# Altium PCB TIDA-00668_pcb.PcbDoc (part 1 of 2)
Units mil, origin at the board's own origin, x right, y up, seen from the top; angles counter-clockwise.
Board outline 2510.03 x 1760.03 mil, 4 copper layers (Component Side 1, Signal Layer 2, Signal Layer 3, Solder Side 4), stack 60.634 mil thick; 105 components, 46 nets, 336 pads, 4 vias.
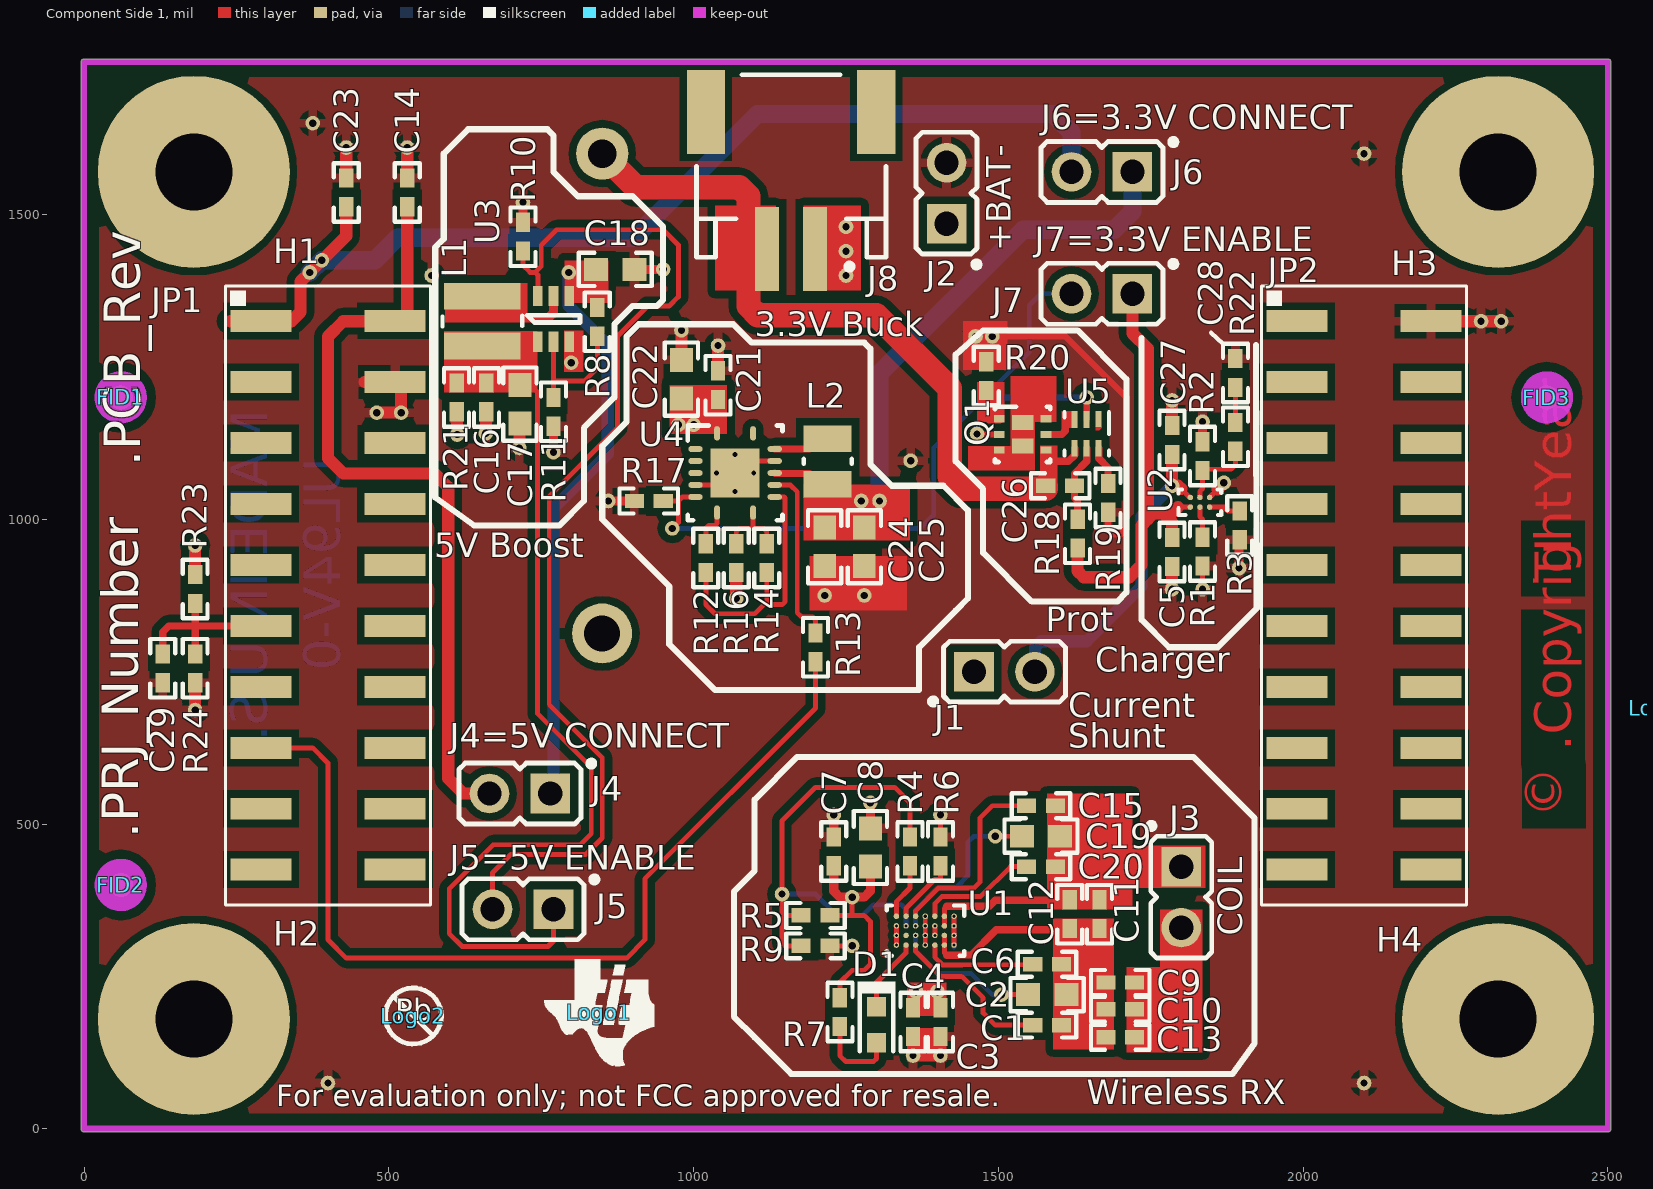
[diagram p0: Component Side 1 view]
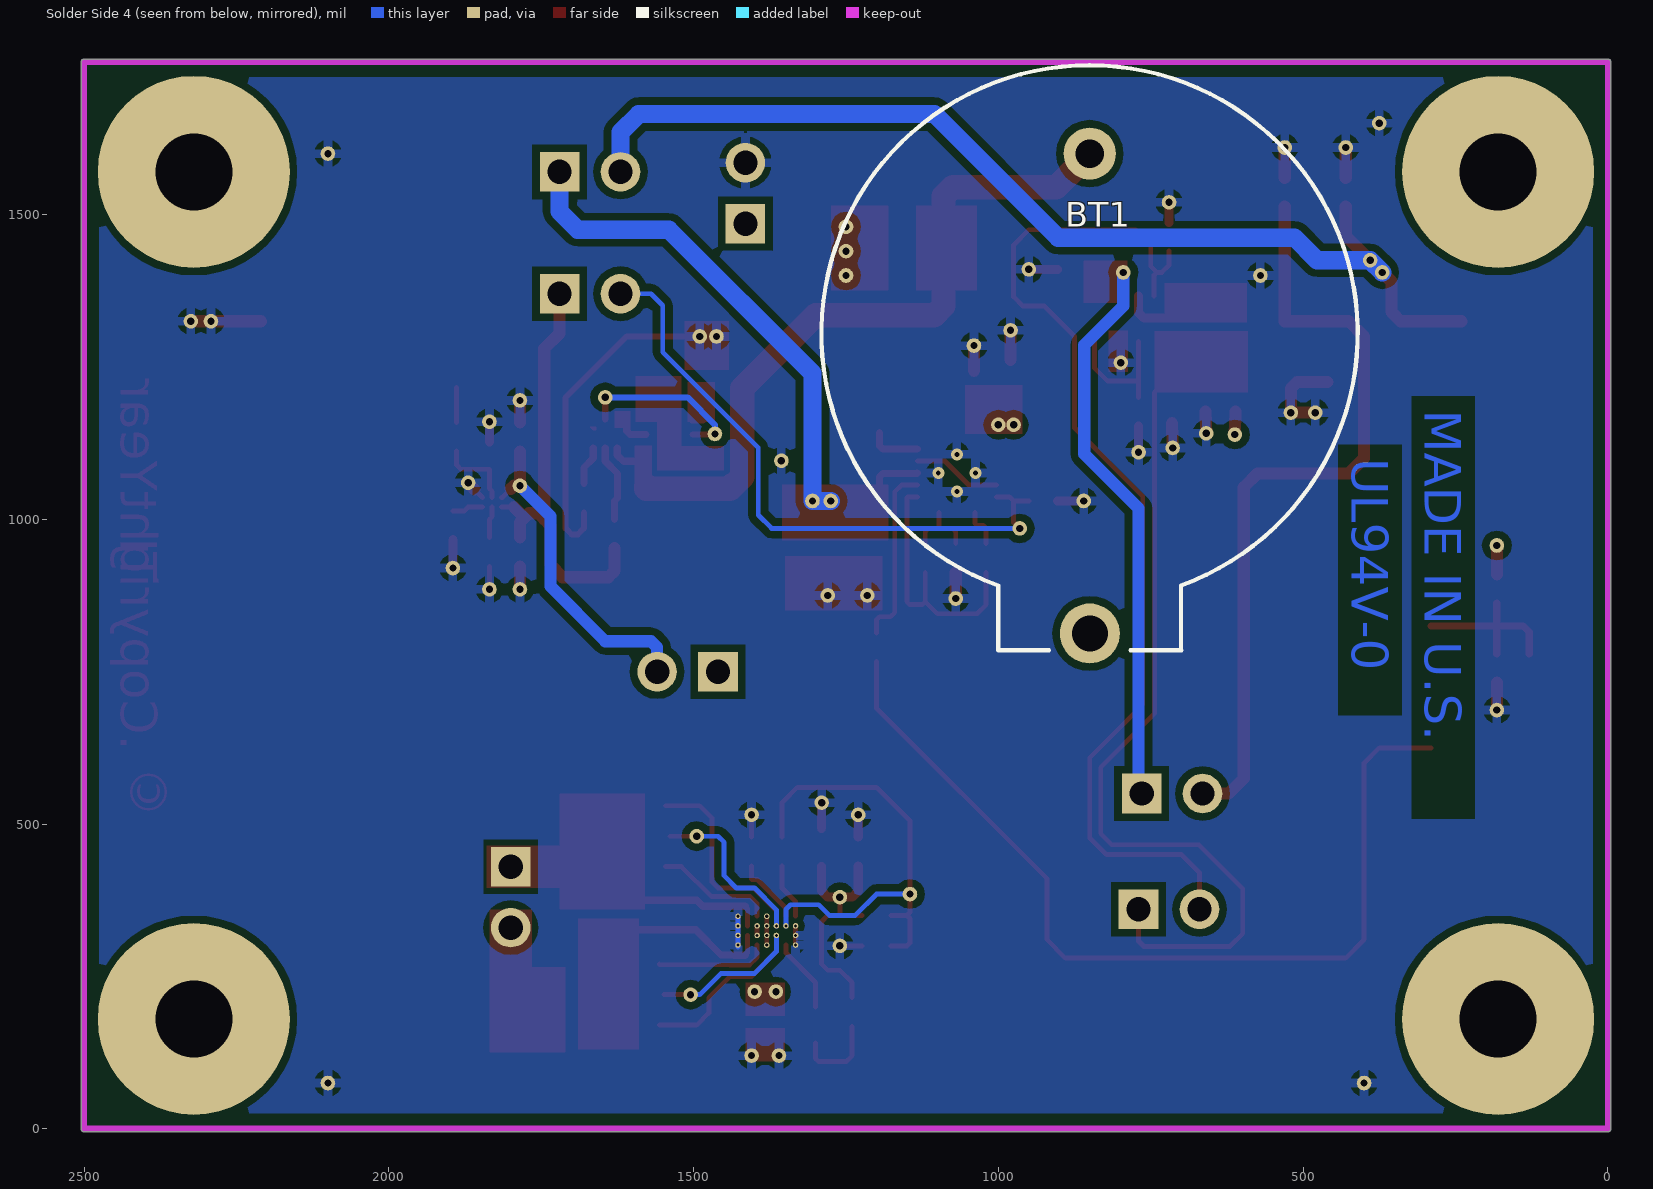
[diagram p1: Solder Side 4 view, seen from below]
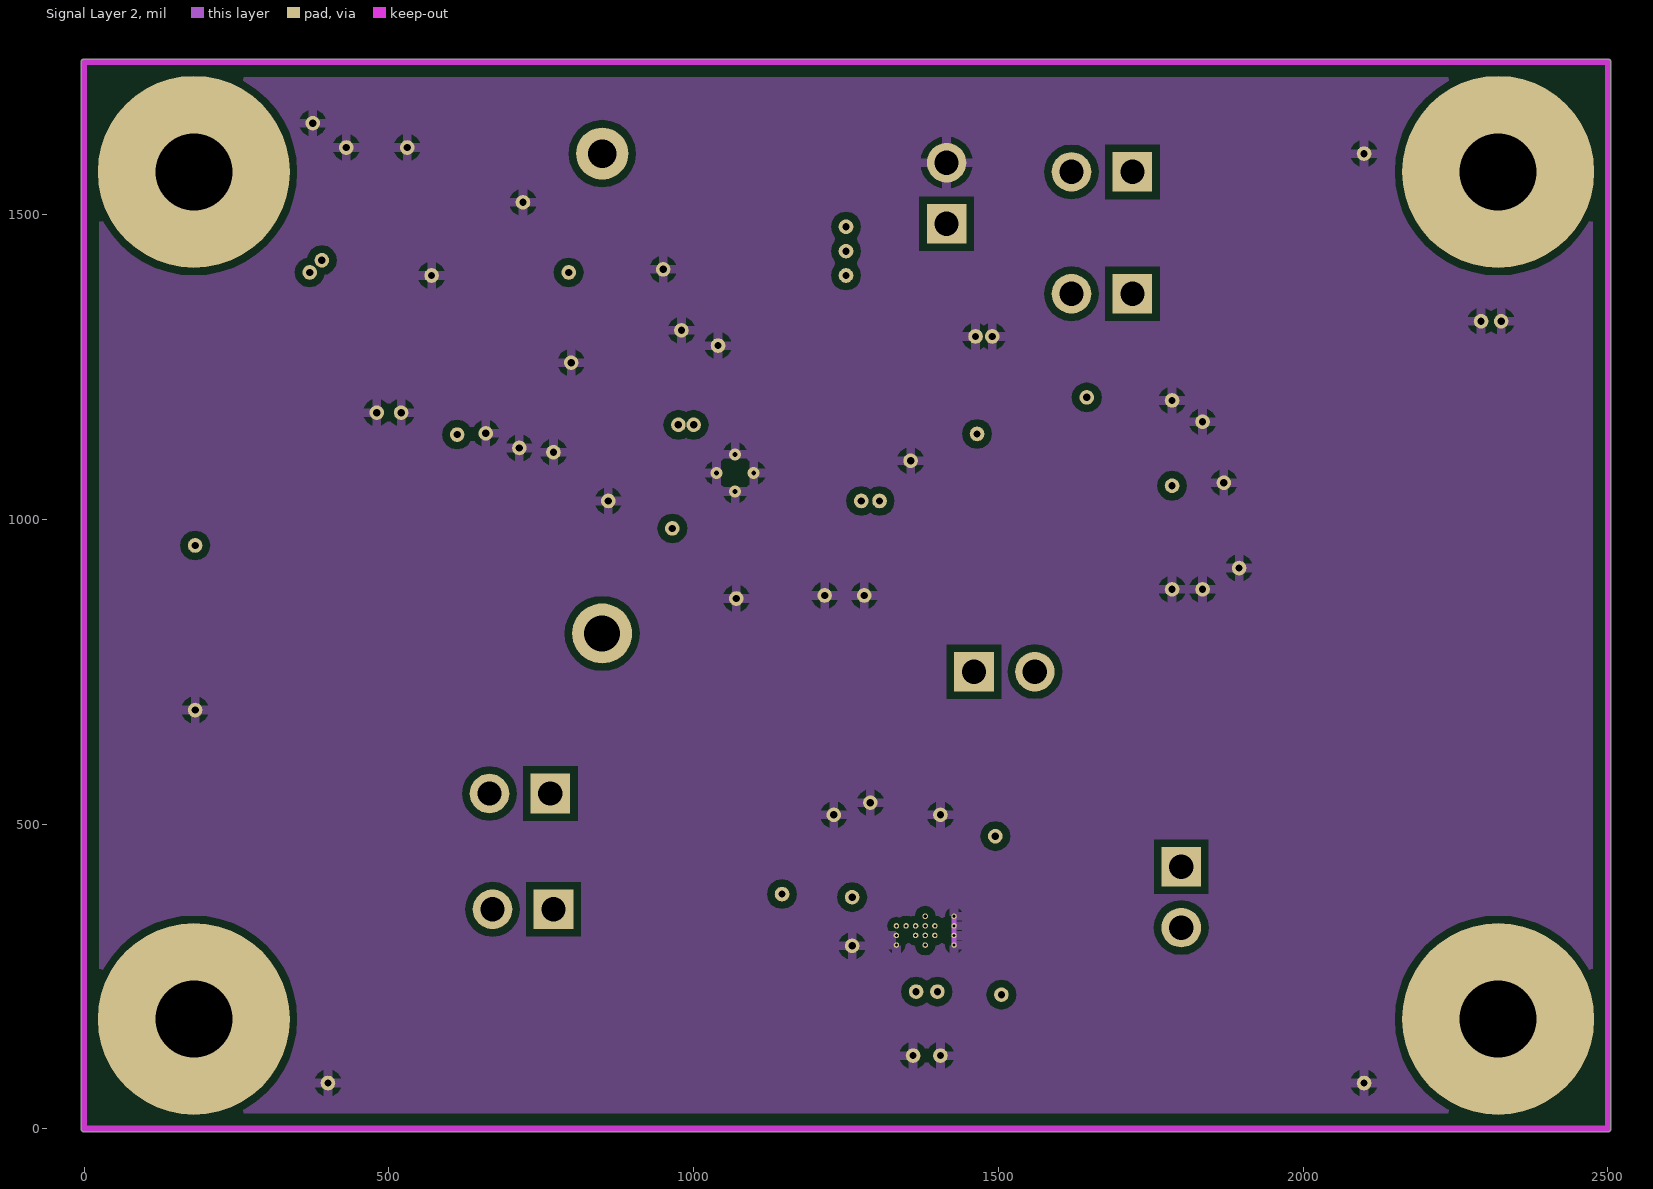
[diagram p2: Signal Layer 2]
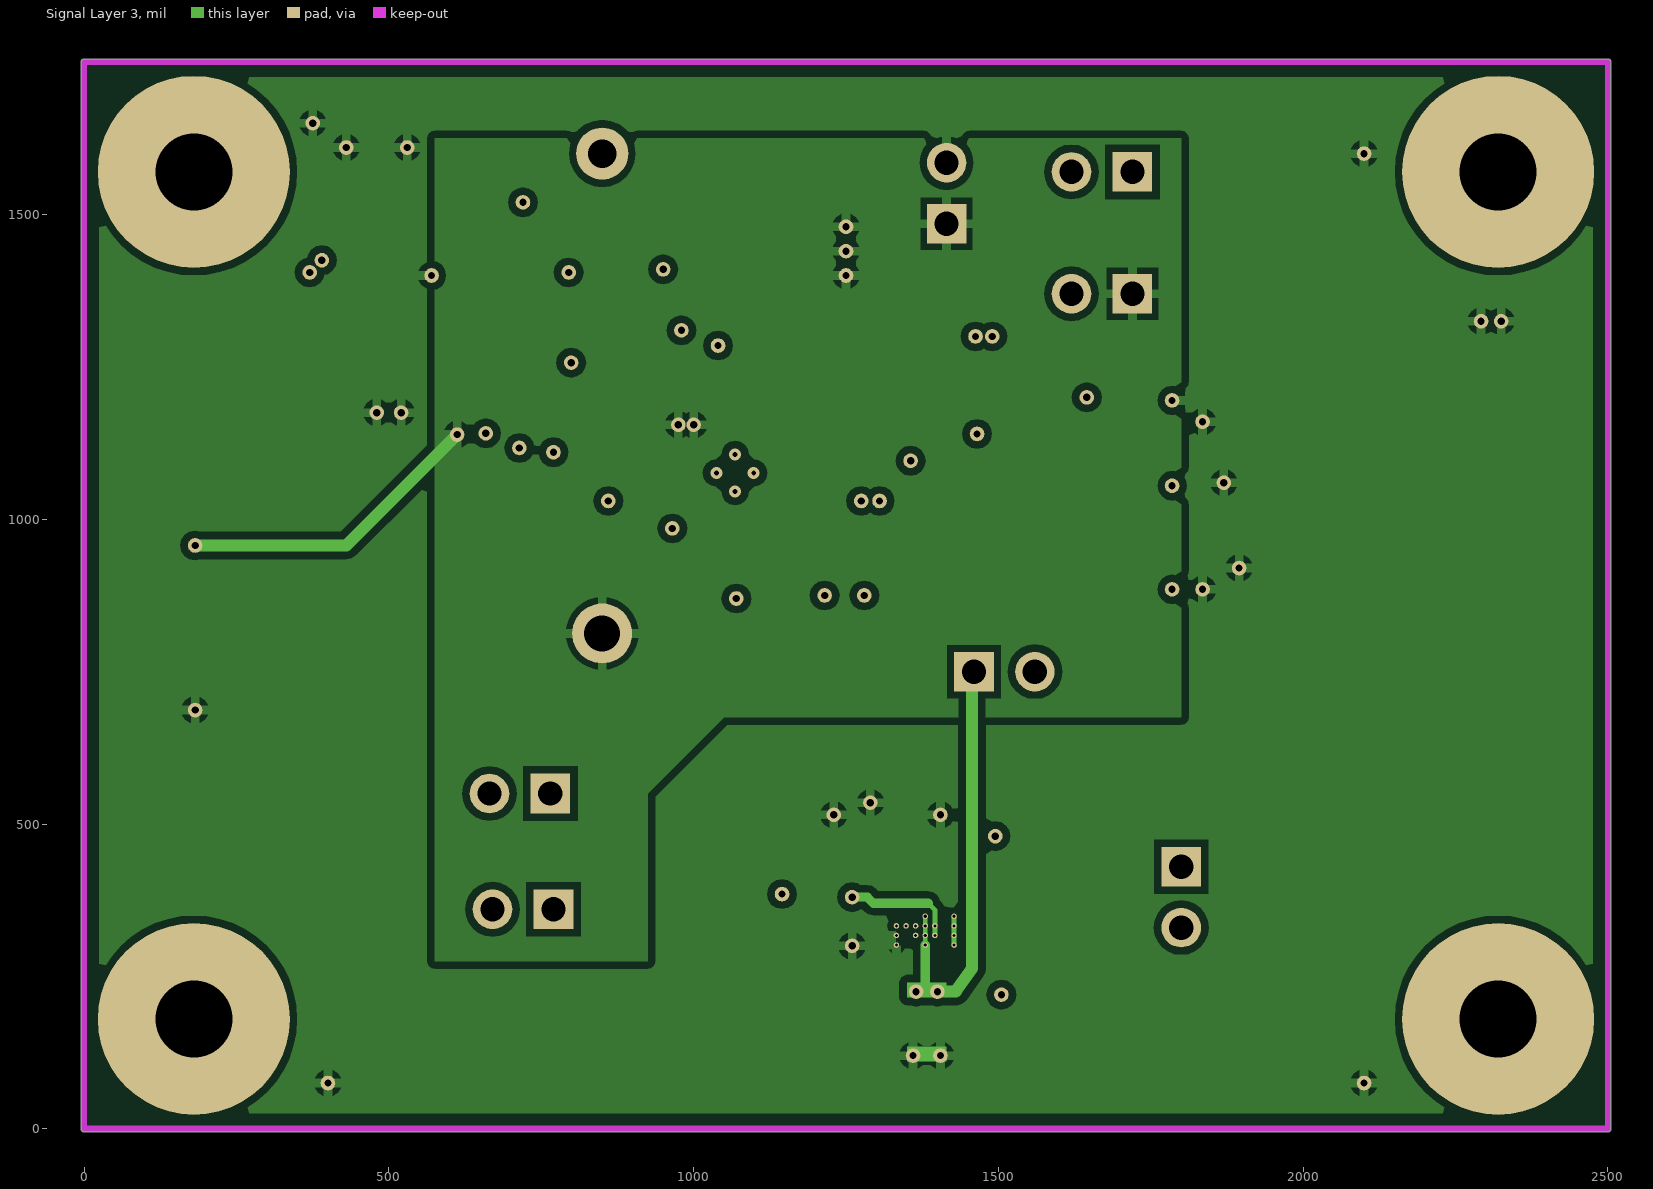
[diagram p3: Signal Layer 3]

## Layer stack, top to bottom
Top Solder: solder mask 0.4, Solder Resist, Dk 3.5
Component Side 1: signal copper 1.4
Dielectric 1: core 10, FR-4HT, Dk 4.2
Signal Layer 2: signal copper 1.417
Dielectric 2: prepreg 35, Dk 4.2
Signal Layer 3: signal copper 1.417
Dielectric 3: core 10, FR-4HT, Dk 4.2
Solder Side 4: signal copper 1.4
Bottom Solder: solder mask 0.4, Solder Resist, Dk 3.5

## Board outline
0,-5.02 cw(c0,0) -5.01,0 -5.01,1750 cw(c0,1750) 0,1755.01 2500,1755.01 cw(c2500,1750) 2505.01,1750 2505.01,0 cw(c2500,0) 2500,-5.02

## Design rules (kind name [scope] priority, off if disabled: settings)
AcuteAngle [All] p1: minimum=4.50000000000000E+0001 checktracksonly=FALSE
AssemblyTestPointUsage [All] p1: valid=2
Clearance Clearance_Keepouts [((IsTrack Or IsArc) And Not InPoly) And IsFree and IsKeepOut vs ((IsTrack Or IsArc) And Not InPoly) And IsFree and IsKeepOut] p1: gap=0
Clearance Clearance_BoardEdge_MountingHoles [OnCopper and InComponentClass('Mounting Holes') vs IsKeepOut] p2: gap=15
Clearance Clearance_BoardEdge_Poly [OnCopper and InPoly vs IsKeepOut] p3: gap=15
Clearance Clearance_BoardEdge [OnCopper and Not InComponentClass('Logo') and not InComponentClass('FiducialMark') and not InRegion(1000,500,4000,800) and Not IsKeepout vs IsKeepOut] p4: gap=40
Clearance Clearance_Poly [InPolygon] p5: gap=12
Clearance [All] p6: gap=3.9
ComponentClearance ComponentClearance_MountingHoles_FiducialMarks [InComponentClass('Mounting Holes') vs InComponentClass('FiducialMark')] p1: gap=50 collisioncheckmode=3 verticalgap=10 showdistances=FALSE
ComponentClearance ComponentClearance_Shunt [InComponentClass('Header') vs InComponentClass('Shunt')] p2: gap=0 collisioncheckmode=3 verticalgap=0 showdistances=FALSE
ComponentClearance ComponentClearance_Logo [InComponentClass('Logo')] p3: gap=30 collisioncheckmode=3 verticalgap=10 showdistances=FALSE
ComponentClearance ComponentClearance_ScrewToNut [(HasFootprint('NY PMS 440 0025 PH')) vs (HasFootprint('Keystone_1902C'))] p4: gap=5 collisioncheckmode=3 verticalgap=10 showdistances=FALSE
ComponentClearance ComponentClearance_MountingHoles [InComponentClass('Mounting Holes')] p5: gap=20 collisioncheckmode=3 verticalgap=100000 showdistances=FALSE
ComponentClearance ComponentClearance_SmallPassives [HasFootprint('0201*') or HasFootprint('0402*') or HasFootprint('0508') or HasFootprint('0603*') or HasFootprint('0612') or HasFootprint('0805*') or HasFootprint('0815*') or HasFootprint('0830*') or HasFootprint('1206*') or HasFootprint('1210*') or HasFootprint('1808*') or HasFootprint('1812*') or HasFootprint('1825*') or HasFootprint('2010*') or HasFootprint('2220*') or HasFootprint('2225*') or HasFootprint('2512*') or HasFootprint('2728*') or HasFootprint('3518*') vs HasFootprint('0201*') or HasFootprint('0402*') or HasFootprint('0508') or HasFootprint('0603*') or HasFootprint('0612') or HasFootprint('0805*') or HasFootprint('0815*') or HasFootprint('0830*') or HasFootprint('1206*') or HasFootprint('1210*') or HasFootprint('1808*') or HasFootprint('1812*') or HasFootprint('1825*') or HasFootprint('2010*') or HasFootprint('2220*') or HasFootprint('2225*') or HasFootprint('2512*') or HasFootprint('2728*') or HasFootprint('3518*')] p6: gap=12 collisioncheckmode=3 verticalgap=12 showdistances=FALSE
ComponentClearance ComponentClearance_THtoSMT [IsThruComponent vs IsSMTComponent] p7: gap=12 collisioncheckmode=3 verticalgap=12 showdistances=FALSE
ComponentClearance ComponentClearance_THtoTH [IsThruComponent vs IsThruComponent] p8: gap=12 collisioncheckmode=3 verticalgap=12 showdistances=FALSE
ComponentClearance [All] p9: gap=12 collisioncheckmode=3 verticalgap=12 showdistances=FALSE
DiffPairsRouting [All] p1: maxlimit=100 minlimit=10 mostfreqgap=10 toplayer_minwidth=15 toplayer_maxwidth=15 toplayer_prefwidth=15 midlayer1_minwidth=15 midlayer1_maxwidth=15 midlayer1_prefwidth=15 midlayer2_minwidth=15 midlayer2_maxwidth=15 midlayer2_prefwidth=15 bottomlayer_minwidth=15 bottomlayer_maxwidth=15 bottomlayer_prefwidth=15 maxuncoupledlength=1000
FabricationTestPointUsage TestPointUsage [All] p1: valid=2 allowmultiple=FALSE
FabricationTestpoint Testpoint [All] p1: side=3 testpointundercomponent=TRUE minsize=40 maxsize=100 preferedsize=60 minholesize=0 maxholesize=40 preferedholesize=32 testpointgrid=1 allowsidetop=TRUE allowsidebottom=TRUE usegrid=TRUE gridtolerance=0.01
FanoutControl Fanout_LCC [IsLCC] p1: bgadir=Out bgaviamode=Centered fanoutstyle=Auto fanoutdirection=Alternating viagrid=1 // Fanout_LCC (Default Rule)
FanoutControl Fanout_BGA [IsBGA] p2: bgadir=Out bgaviamode=Centered fanoutstyle=Auto fanoutdirection=Alternating viagrid=1 // Fanout_BGA (Default Rule)
FanoutControl Fanout_Default [All] p4: bgadir=Out bgaviamode=Centered fanoutstyle=Auto fanoutdirection=Alternating viagrid=1 // Fanout_Default (Default Rule)
FanoutControl Fanout_Small [(CompPinCount < 5)] p5: bgadir=Out bgaviamode=Centered fanoutstyle=Auto fanoutdirection=OutThenIn viagrid=1 // Fanout_Small (Default Rule)
HoleSize [All] p1: absolutevalues=TRUE maxlimit=251 minlimit=5 maxpercent=80.000 minpercent=20.000
MinimumAnnularRing MinimumAnnularRing_ThermalPadVias [IsVia and InAnyComponent] p1: minimumring=5.91
MinimumAnnularRing [All] p2: minimumring=6
MinimumSolderMaskSliver MinimumSolderMaskSliver_Logo [InComponentClass('Logo') vs InComponentClass('Logo')] p1: minsoldermaskwidth=0.7
MinimumSolderMaskSliver [All] p2: minsoldermaskwidth=3.94
PlaneClearance [All] p1: clearance=10
PlaneConnect [All] p1: planeconnectstyle=Relief reliefexpansion=10 reliefentries=4 reliefconductorwidth=10 reliefairgap=10
PolygonConnect [All] p1: connectstyle=Relief reliefconductorwidth=15 reliefentries=4 polygonreliefangle="90 Angle" airgapwidth=10
RoutingVias ThermalPadVias [IsVia and InAnyComponent] p1: holewidth=7.87 width=19.68 viastyle="Through Hole" minholewidth=7.87 minwidth=19.68 maxholewidth=12.99 maxwidth=23.62
RoutingVias [All] p2: holewidth=16 width=34 viastyle="Through Hole" minholewidth=7.87 minwidth=26 maxholewidth=40 maxwidth=65
SilkToBoardRegionClearance [Not ((IsComment or IsDesignator) And (Hide <> 'False')) and not InRegion(1000,500,4000,800)] p1:
SilkToSilkClearance SilkToSilkClearance_Pb-FreeLogo [(HasFootprint('Pb-Free_Overlay_Medium') OR HasFootprint('Pb-Free_Overlay_Small')) vs (HasFootprint('Pb-Free_Overlay_Medium') OR HasFootprint('Pb-Free_Overlay_Small'))] p1: silktosilkclearance=0
SilkToSilkClearance [All] p2: silktosilkclearance=5
SilkToSolderMaskClearance "Silk to Solder Mask Opening" [All] p1: minsilkscreentomaskgap=1 clearancetoexposedcopper=FALSE
SolderMaskExpansion [All] p1: expansion=1.97
UnpouredPolygon [All] p1: allowunpoured=FALSE
Width [All] p1: maxlimit=100 minlimit=6 preferedwidth=10 checkconnectedcopper=TRUE
13 further rules are at their usual default settings.

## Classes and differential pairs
component class Shunt: SH-J1 SH-J4 SH-J5 SH-J6 SH-J7
component class "Mounting Holes": H1 H2 H3 H4 H5 H6 H7 H8
component class Header: J1 J2 J3 J4 J5 J6 J7 JP1 JP2
component class TIDA-00668_sch: BT1 C1 C2 C3 C4 C5 C6 C7 C8 C9 C10 C11 C12 C13 C14 C15 C16 C17 C18 C19 C20 C21 C22 C23 C24 C25 C26 C27 C28 C29 D1 J1 J2 J3 J4 J5 J6 J7 J8 JP1 JP2 L1 L2 Q1 R1 R2 R3 R4 R5 R6 R7 R8 R9 R10 R11 R12 R13 R14 R16 R17 R18 R19 R20 R21 R22 R23 R24 U1 U2 U3 U4 U5
component class Logo: Logo1
component class TIDA-00668_hdw: "Coil 1" "Ferrite 1" FID1 FID2 FID3 H1 H2 H3 H4 H5 H6 H7 H8 HS5 HS6 HS7 HS8 Logo1 Logo2 Logo3 SH-J1 SH-J4 SH-J5 SH-J6 SH-J7 ZZ1 ZZ2 ZZ3 ZZ4 ZZ5 ZZ6 ZZ7 ZZ8
component class FiducialMark: FID1 FID2 FID3
component class AssemblyNote: ZZ1 ZZ2 ZZ3 ZZ4 ZZ5 ZZ6 ZZ7 ZZ8
component class EMI: "Coil 1" "Ferrite 1"

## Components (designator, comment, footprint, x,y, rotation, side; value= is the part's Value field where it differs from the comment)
BT1 "BS-7" BAT_BS-7 850,1206.3 r90 bottom locked
C1 "C1005X8R1H472K" 0402 1580,170 r0 top
C2 "GRM188R71E474KA12D" 0603 1580,220 r0 top
C3 "GRM155R71A104KA01D" 0402 1405,175 r270 top
C4 "C1005X5R1A475K050BC" 0402 1360,175 r270 top
C5 "C1005X5R1A475K050BC" 0402 1785,946.38 r270 top
C6 "C0402C103J5RACTU" 0402 1580,270 r0 top
C7 "C1005X7R1C223K" 0402 1230,455 r90 top
C8 "GRM188R61C475KAAJ" 0603 1290,461.5 r90 top
C9 "C0402C103J5RACTU" 0402 1700,240 r0 top
C10 "C0402C103J5RACTU" 0402 1700,196 r0 top
C11 "GRM1555C1H221JA01D" 0402 1666,352 r90 top
C12 "GRM1555C1H221JA01D" 0402 1617,352 r90 top
C13 "C1005X8R1H472K" 0402 1700,150 r0 top
C14 "GRM155R71A104KA01D" 0402 530,1536.38 r90 top
C15 "C1005X8R1H472K" 0402 1570,530 r0 top
C16 "GRM155R71A104KA01D" 0402 660,1200 r270 top
C17 "C0603C106M9PACTU" 0603 715,1189 r270 top
C18 "C0603C106M9PACTU" 0603 871.5,1410 r0 top
C19 "GRM188R71E474KA12D" 0603 1570,480 r0 top
C20 "C0402C103J5RACTU" 0402 1570,430 r0 top
C21 "GRM155R71A104KA01D" 0402 1040,1220 r90 top
C22 "C0603C106M9PACTU" 0603 980,1230 r90 top
C23 "GRM155R71A104KA01D" 0402 430,1536.38 r90 top
C24 "C0603C106M9PACTU" 0603 1215,955 r270 top
C25 "C0603C106M9PACTU" 0603 1280,955 r270 top
C26 "GRM155R71A104KA01D" 0402 1601.38,1055 r180 top
C27 "GRM155R71A104KA01D" 0402 1785,1130 r90 top
C28 "C0402C103J5RACTU" 0402 1889,1240 r90 top
C29 "GRM155R71A104KA01D" 0402 129,755.38 r270 top
"Coil 1" "760308103206" SIL-PAD_24X21MM 375,5725 r90 top
D1 "LTST-C190GKT" LED_LTST-C190 1300,170.47 r90 top
"Ferrite 1" "WE-FSFS" SIL-PAD_24X21MM 390,6905 r90 top
FID1 "Fiducial" Fiducial10-20 60,1200 r0 top
FID2 "Fiducial" Fiducial10-20 60,400 r0 top
FID3 "Fiducial" Fiducial10-20 2400,1200 r0 top
H1 "NY PMS 440 0025 PH" "NY PMS 440 0025 PH" 180,1570 r0 top
H2 "NY PMS 440 0025 PH" "NY PMS 440 0025 PH" 180,180 r0 top
H3 "NY PMS 440 0025 PH" "NY PMS 440 0025 PH" 2320,1570 r0 top
H4 "NY PMS 440 0025 PH" "NY PMS 440 0025 PH" 2320,180 r0 top
H5 "NY PMS 440 0025 PH" "NY PMS 440 0025 PH" 1600,2395 r0 top
H6 "NY PMS 440 0025 PH" "NY PMS 440 0025 PH" 2000,2395 r0 top
H7 "NY PMS 440 0025 PH" "NY PMS 440 0025 PH" 2405,2400 r0 top
H8 "NY PMS 440 0025 PH" "NY PMS 440 0025 PH" 2815,2385 r0 top
HS5 "1902B" Keystone_1902B 1150.36,2390 r180 top
HS6 "1902B" Keystone_1902B 128.36,2386 r180 top
HS7 "1902B" Keystone_1902B 468.36,2386 r180 top
HS8 "1902B" Keystone_1902B 818.36,2386 r180 top
J1 "PBC02SAAN" Sullins_PBC02SAAN 1510,750 r90 top
J2 "PBC02SAAN" Sullins_PBC02SAAN 1415,1535.14 r180 top
J3 "PBC02SAAN" Sullins_PBC02SAAN 1800,380 r0 top
J4 "PBC02SAAN" Sullins_PBC02SAAN 715,550 r270 top
J5 "PBC02SAAN" Sullins_PBC02SAAN 720,360 r270 top
J6 "PBC02SAAN" Sullins_PBC02SAAN 1670,1570 r270 top
J7 "PBC02SAAN" Sullins_PBC02SAAN 1670,1370 r270 top
J8 "S2B-PH-SM4-TB(LF)(SN)" JST_S2B-PH-SM4-TB 1160,1560 r180 top
JP1 "TSM-110-01-T-DV-P" CONN_TSM-110-01-T-DV-P 400,875 r270 top locked
JP2 "TSM-110-01-T-DV-P" CONN_TSM-110-01-T-DV-P 2100,875 r270 top locked
L1 "EPL3015-472MLB" EPL3015 653,1325 r90 top
L2 "74404024100" WE_LQS_252012 1220,1095 r270 top
Logo1 "Texas Instruments" TI_Symbol_Overlay_Small 845,190 r0 top
Logo2 "Pb-Free Symbol" Pb-Free_Overlay_Small 540,185 r0 top
Logo3 "FCC disclaimer" FCC_disclaimer 2588,691 r90 top
Q1 "CSD85301Q2" DQK0006B 1540,1139.21 r0 top
R1 "CRCW040210K0FKED" 0402 1835,947 r90 top
R2 "CRCW04025K36FKED" 0402 1835,1103.62 r270 top
R3 "CRCW04024K87FKED" 0402 1896,990 r90 top
R4 "CRCW04021K30FKED" 0402 1355,455 r270 top
R5 "CRCW040220K0FKED" 0402 1200,350 r0 top
R6 "CRCW040210K0FKED" 0402 1405,455 r270 top
R7 "CRCW04021K50FKED" 0402 1240,191.38 r90 top
R8 "CRCW04021M00FKED" 0402 842,1324 r90 top
R9 "CRCW0402196RFKED" 0402 1200,300 r180 top
R10 "CRCW04021M00FKED" 0402 720,1463.62 r270 top
R11 "CRCW0402110KFKED" 0402 770,1176.38 r90 top
R12 "CRCW04028M06FKED" 0402 1020,936.38 r90 top
R13 "CRCW04020000Z0ED" 0402 1200,790 r90 top
R14 "CRCW0402140KFKED" 0402 1120,936.38 r270 top
R16 "CRCW04024M53FKED" 0402 1070,936.38 r90 top
R17 "CRCW04021M00FKED" 0402 926.38,1030 r0 top
R18 "CRCW0402221RFKED" 0402 1630,976.38 r270 top
R19 "CRCW04022K21FKED" 0402 1680,1035 r90 top
R20 "ERJ-2BQFR82X" 0402 1480,1235 r270 top
R21 "CRCW04020000Z0ED" 0402 611,1200 r90 top
R22 "CRCW04022K70JNED" 0402 1889,1135.38 r270 top
R23 "CRCW04021M00FKED" 0402 182,885.62 r90 top
R24 "CRCW04021M00FKED" 0402 182,755.38 r90 top
SH-J1 "969102-0000-DA" SNT-100-BK-G 118,2956 r90 top
SH-J4 "969102-0000-DA" SNT-100-BK-G 398,2956 r90 top
SH-J5 "969102-0000-DA" SNT-100-BK-G 688,2956 r90 top
SH-J6 "969102-0000-DA" SNT-100-BK-G 978,2956 r90 top
SH-J7 "969102-0000-DA" SNT-100-BK-G 1268,2956 r90 top
U1 "BQ51003YFPR" YFP0028APAL 1380,325 r270 top
U2 "BQ25100YFP" YFP0006AFAV 1830.75,1027.87 r90 top
U3 "TPS61220DCK" DCK0006A_N 770,1329 r90 top
U4 "TPS62736RGYR" RGY0014A 1068,1076 r0 top
U5 "BQ29707DSER" DSE0006A 1645,1140 r270 top
ZZ1 "These assemblies are ESD sensitive, ESD precautions shall be observed." AssemblyNote 250,4825 r0 top
ZZ2 "These assemblies must be clean and free from flux and all contaminants. Use of no clean flux is not acceptable." AssemblyNote 250,4725 r0 top
ZZ3 "These assemblies must comply with workmanship standards IPC-A-610 Class 2, unless otherwise specified." AssemblyNote 250,4625 r0 top
ZZ4 "Wireless Coil 1 will be attached to the PCB C02 on the bottom of the board stack. The wires will be soldered to the PCB." AssemblyNote 250,4525 r0 top
ZZ5 "The Ferrite Shield must be custom cut to fit the PCB. Only the four mounting holes are allowed." AssemblyNote 250,4425 r0 top
ZZ6 "Nylon screws and spacers only for this assembly. The only copper on PCB C01 and C02 is for the wire holes. No extra copper is allowed on PCB C01 and C02." AssemblyNote 250,4325 r0 top
ZZ7 "Use 2 strands, 3 inch Length, of 26 gauge litz wire to connect the PCB C02 board to the main PCB connector J3. Attach the litz wire to PCB C01 and leave hanging." AssemblyNote 250,4225 r0 top
ZZ8 "The assembly build will use PCB C02. Bag and ship PCB C01 with the assembly." AssemblyNote 250,4125 r0 top

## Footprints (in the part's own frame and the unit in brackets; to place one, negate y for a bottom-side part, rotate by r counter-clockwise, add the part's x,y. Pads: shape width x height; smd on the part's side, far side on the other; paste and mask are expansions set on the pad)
0402 [mm] "0402 from SM-752 data"
  rect 0.8x0.6 smd: 1(-0.6,0) 2(0.6,0)
  silkscreen extent -1.22,-0.52 1.22,0.52, body extent -0.55,-0.3 0.55,0.3, height 0.6
0603 [mm] "0603 from SM-752 data"
  rect 1x0.95 smd: 1(-0.8,0) 2(0.8,0)
  silkscreen extent -1.52,-0.69 1.52,0.69, body extent -0.87,-0.47 0.87,0.47, height 0.85
AssemblyNote [mil] "Assembly Note"
BAT_BS-7 [mm] "Memory Protection Devices CR2032 battery holder"
  round 2.5 hole 1.5: 1(-10,0)
  round 2.17 hole 1.181: 2(10,0)
  silkscreen extent -10.7,-11.16 13.68,11.18, body extent -10.69,-11.16 13.7,11.16, height 9.02
CONN_TSM-110-01-T-DV-P [mil]
  rect 36x100 smd mask+2: 1(-450,-110) 2(-450,110) 3(-350,-110) 4(-350,110) 5(-250,-110) 6(-250,110) 7(-150,-110) 8(-150,110) 9(-50,-110) 10(-50,110) 11(50,-110) 12(50,110) 13(150,-110) 14(150,110) 15(250,-110) 16(250,110) 17(350,-110) 18(350,110) 19(450,-110) 20(450,110)
  silkscreen extent -508,-168 508,168, body extent -500,-145 500,145, height 380
DCK0006A_N [mm] "SOT23, 6-Leads, Body 2x1.3mm, Pitch 0.65mm, Lead Span 2.1mm, IPC Medium Density"
  rect 0.85x0.4 smd: 1(-0.95,0.65) 2(-0.95,0) 3(-0.95,-0.65) 4(0.95,-0.65) 5(0.95,0) 6(0.95,0.65)
  silkscreen extent -0.15,-1.1 0.15,1.1, body extent -1.14,-1 1.14,1, height 0.94
DQK0006B [mm] "TI"
  rect 0.45x0.3 smd: 1(-0.975,0.65) 2(-0.975,0) 3(-0.975,-0.65) 4(0.975,-0.65) 5(0.975,0) 6(0.975,0.65)
  rect 0.9x0.625 smd paste-0.025: 7(0,0.488) 8(0,-0.488)
  silkscreen extent -1.15,-1.15 1.15,1.15, body extent -1.05,-1.05 1.05,1.05, height 0.8
DSE0006A [mm] "TI recommended land pattern"
  rect 0.66x0.25 smd: 1(-0.62,0.5)
  rect 0.7x0.25 smd: 2(-0.6,0) 3(-0.6,-0.5) 4(0.6,-0.5) 5(0.6,0) 6(0.6,0.5)
  Component Side 1 region: -0.3,0.625 -0.25,0.625 -0.15,0.525 -0.15,0.375 -0.3,0.375
  silkscreen extent -0.9,-0.92 0.9,0.92, body extent -0.77,-0.77 0.77,0.77, height 0.8
EPL3015 [mm] "COILCRAFT"
  rect 1.12x3.2 smd: 1(-1.04,0) 2(1.04,0)
  silkscreen extent -0.22,-1.68 0.23,1.65, body extent -1.6,-1.6 1.6,1.6, height 1.55
FCC_disclaimer [mil]
Fiducial10-20 [mm]
  round 1 smd mask+0.5: 1(0,0)
  Component Side 1 keep-out circle w1.178: c0,0 r0.5
JST_S2B-PH-SM4-TB [mm] "JST Sales America Inc"
  rect 1x3.5 smd paste+0 mask+0.05: 1(-1,2.95) 2(1,2.95)
  rect 1.6x3.5 smd paste+0 mask+0.05: M1(-3.55,-2.75) M2(3.55,-2.75)
  silkscreen extent -3.95,-4.3 3.95,3.79, body extent -3.95,-4.3 3.95,4.3, height 5.62
Keystone_1902B [mil] "Hex Standoff, 4-40 threaded, nylon"
  round 1 on Mech4: 0(0,0)
  body extent -145,-126 145,126, height 375
LED_LTST-C190 [mm] "Lite-On"
  rect 0.8x0.8 smd: 1(-0.75,0) 2(0.75,0)
  silkscreen extent -1.1,-0.8 1.8,0.8, body extent -0.85,-0.45 0.85,0.45, height 0.9
"NY PMS 440 0025 PH" [mm] "4-40 nylon screw and mounting hole"
  round 8 hole 3.2: 1(0,0)
  body extent -3.3,-3.3 3.3,3.3, height 2.69
Pb-Free_Overlay_Small [mil]
  silkscreen extent -46,-46 46,46
RGY0014A [mm] "QFN, 14-Leads, Body 3.5x3.5mm, Pitch 0.5mm, Thermal Pad 2.05x2.05mm, TI Recommended"
  oval 0.24x0.6 smd: 1(-0.75,1.65) 7(-0.75,-1.65) 8(0.75,-1.65) 14(0.75,1.65)
  oval 0.6x0.24 smd: 2(-1.65,1) 3(-1.65,0.5) 4(-1.65,0) 5(-1.65,-0.5) 6(-1.65,-1) 9(1.65,-1) 10(1.65,-0.5) 11(1.65,0) 12(1.65,0.5) 13(1.65,1)
  rect 2.05x2.05 smd paste-1.025: 15(0,0)
  silkscreen extent -1.98,-1.97 1.98,1.97, body extent -1.83,-1.83 1.82,1.82, height 1.01
SIL-PAD_24X21MM [mil] "Sil-Pad"
  silkscreen extent -482,-423 482,423, body extent -472,-413 472,413, height 9
SNT-100-BK-G [mil] "Samtec STEP model"
  round 1 on Mech3: 0(0,0)
  body extent -100,-50 100,50, height 344
Sullins_PBC02SAAN [mm] "Sullins 100mil, 1x2, 230 mil above insulator"
  rect 1.65x1.65 hole 1.016: 1(0,1.27)
  round 1.65 hole 1.016: 2(0,-1.27)
  silkscreen extent -1.37,-2.54 1.27,3.1, body extent -1.27,-2.54 1.27,2.54, height 8.38
TI_Symbol_Overlay_Small [mil]
  silkscreen extent -90,-88 91,88
WE_LQS_252012 [mm] "SMD, 2-Leads, Body 2.5x2mm, Pitch 1.9mm"
  rect 1.1x2 smd: 1(-0.95,0) 2(0.95,0)
  silkscreen extent -0.1,-1 0.1,1, body extent -1.25,-1 1.25,1, height 1.2
YFP0006AFAV [mm] "TI DSBGA 0.88x1.58mm"
  round 0.23 smd paste-0.13 mask+0.038: A1(-0.2,0.4) A2(0.2,0.4) B1(-0.2,0) B2(0.2,0) C1(-0.2,-0.4) C2(0.2,-0.4)
  silkscreen extent -0.53,-0.89 0.53,0.89, body extent -0.46,-0.8 0.46,0.81, height 0.51
YFP0028APAL [mm] "BGA, 28-Leads, Body 3.046x1.923mm,  Pitch 0.4mm"
  round 0.23 smd paste-0.2 mask+0.04: A1(-0.6,1.2) A2(-0.2,1.2) A3(0.2,1.2) A4(0.6,1.2) B1(-0.6,0.8) B2(-0.2,0.8) B3(0.2,0.8) B4(0.6,0.8) C1(-0.6,0.4) C2(-0.2,0.4) C3(0.2,0.4) C4(0.6,0.4) D1(-0.6,0) D2(-0.2,0) D3(0.2,0) D4(0.6,0) E1(-0.6,-0.4) E2(-0.2,-0.4) E3(0.2,-0.4) E4(0.6,-0.4) F1(-0.6,-0.8) F2(-0.2,-0.8) F3(0.2,-0.8) F4(0.6,-0.8) G1(-0.6,-1.2) G2(-0.2,-1.2) G3(0.2,-1.2) G4(0.6,-1.2)
  silkscreen extent -1.05,-1.6 1.05,1.63, body extent -0.96,-1.52 0.96,1.52, height 0.51

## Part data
BT1: "Battery Holder, CR2032, Retainer clip, TH"
C1 C13 C15: "CAP, CERM, 4700 pF, 50 V, +/- 10%, X8R, 0402"
C2 C19: "CAP, CERM, 0.47 µF, 25 V, +/- 10%, X7R, 0603"
C3 C14 C16 C21 C23 C26 C27 C29: "CAP, CERM, 0.1uF, 10V, +/-10%, X7R, 0402"
C4 C5: "CAP, CERM, 4.7 µF, 10 V, +/- 10%, X5R, 0402"
C6 C9 C10 C20 C28: "CAP, CERM, 0.01 µF, 50 V, +/- 5%, X7R, 0402"
C7: "CAP, CERM, 0.022 µF, 16 V, +/- 10%, X7R, 0402"
C8: "CAP, CERM, 4.7 µF, 16 V, +/- 10%, X5R, 0603"
C11 C12: "CAP, CERM, 220 pF, 50 V, +/- 5%, C0G/NP0, 0402"
C17 C18 C22 C24 C25: "CAP, CERM, 10 µF, 6.3 V, +/- 20%, X5R, 0603"
"Coil 1": library part SP900S-0.009-00-114, "Wireless coil"
D1: "LED, Green, SMD"
"Ferrite 1": library part SP900S-0.009-00-114, "Ferrite shield"
FID1 FID2 FID3: "Fiducial mark.  There is nothing to buy or mount."
H1 H2 H3 H4 H5 H6 H7 H8: "Machine Screw, Round, #4-40 x 1/4, Nylon, Philips panhead"
HS5 HS6 HS7 HS8: "Standoff, Hex, 0.375\"L #4-40 Nylon"
J1 J2 J3 J4 J5 J6 J7: "Header, 100mil, 2x1, Gold, TH"
J8: "Header (shrouded), 2mm, 2x1, R/A, SMT"
JP1 JP2: "Header, 100mil, 10x2, Tin, SMT"
L1: "Inductor, Shielded, Ferrite, 4.7 µH, 1.2 A, 0.14 ohm, SMD"
L2: "Inductor, Wirewound, Ferrite, 10 µH, 0.47 A, 0.435 ohm, SMD"
Logo1: library part TI_Logo, "Texas Instrument Corporate Signature"
Logo2: library part Pb-Free
Logo3: library part FCC_disclaimer, "FCC_disclaimer"
Q1: "MOSFET, N-CH, 20 V, 6.7 A, SMD, 2.0x2.0, Height 0.8mm"
R1 R6: "RES, 10.0 k, 1%, 0.063 W, 0402"
R2: "RES, 5.36 k, 1%, 0.063 W, 0402"
R3: "RES, 4.87 k, 1%, 0.063 W, 0402"
R4: "RES, 1.30 k, 1%, 0.063 W, 0402"
R5: "RES, 20.0 k, 1%, 0.063 W, 0402"
R7: "RES, 1.50 k, 1%, 0.063 W, 0402"
R8 R10 R17 R23 R24: "RES, 1.00 M, 1%, 0.063 W, 0402"
R9: "RES, 196, 1%, 0.063 W, 0402"
R11: "RES, 110 k, 1%, 0.063 W, 0402"
R12: "RES, 8.06 M, 1%, 0.063 W, 0402"
R13 R21: "RES, 0, 5%, 0.063 W, 0402"
R14: "RES, 140 k, 1%, 0.063 W, 0402"
R16: "RES, 4.53 M, 1%, 0.063 W, 0402"
R18: "RES, 221, 1%, 0.063 W, 0402"
R19: "RES, 2.21 k, 1%, 0.063 W, 0402"
R20: "RES, 0.82, 1%, 0.125 W, 0402"
R22: "RES, 2.7 k, 5%, 0.063 W, 0402"
SH-J1 SH-J4 SH-J5 SH-J6 SH-J7: "Shunt, 100mil, Gold plated, Black"
U1: "Highly Integrated Wireless Receiver Qi (WPC v1.1) Compliant Power Supply, YFP0028APAL"
U2: "400 mA Single-Input, Single Cell Li-Ion Battery Chargers, YFP0006AFAV"
U3: "LOW INPUT VOLTAGE STEP-UP CONVERTER IN 6 PIN SC-70 PACKAGE, DCK0006A"
U4: "Programmable Output Voltage Ultra-Low Power Buck Converter With Up to 50 mA Output Current, RGY0014A"
U5: library part BQ29700DSER, "Cost-Effective Voltage and Current Protection Integrated Circuit for Single-Cell Li-Ion/Li-Polymer Batteries, DSE0006A"
ZZ1 ZZ2 ZZ3 ZZ4 ZZ5 ZZ6 ZZ7 ZZ8: library part AssemblyNote

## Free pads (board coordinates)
  round 24 hole 12: 0(182,687) 0(182,957) 0(370,1405) 0(375,1650) 0(390,1425) 0(400,75) 0(430,1610) 0(480,1175) 0(520,1175) 0(530,1610) 0(570,1400) 0(612,1139) 0(659,1141) 0(714,1117) 0(720,1520) 0(770,1110) 0(795,1405) 0(799,1257) 0(860,1030) 0(950,1410) 0(965,985) 0(975,1155) 0(980,1310) 0(1000,1155) 0(1040,1285) 0(1070,870) 0(1145,385) 0(1215,875) 0(1230,515) 0(1250,1400) 0(1250,1440) 0(1250,1480) 0(1260,300) 0(1260,380) 0(1275,1030) 0(1280,875) 0(1290,535) 0(1305,1030) 0(1356,1096) 0(1360,120) 0(1365,225) 0(1400,225) 0(1405,120) 0(1405,515) 0(1462.5,1300) 0(1465,1140) 0(1490,1300) 0(1495,480) 0(1505,220) 0(1645,1200) 0(1785,885) 0(1785,1055) 0(1785,1195) 0(1835,885) 0(1835,1160) 0(1870,1060) 0(1895,920) 0(2100,75) 0(2100,1600) 0(2292,1325) 0(2325,1325)
  round 9 hole 5 paste+2 mask+2: 0(1332.7,317.1) 0(1332.75,332.85) 0(1332.76,301.38) 0(1348.5,332.85) 0(1364.25,317.1) 0(1364.25,332.85) 0(1380,317.13) 0(1380,332.9) 0(1380,348.65) 0(1380.01,301.37) 0(1395.75,317.1) 0(1395.75,332.85) 0(1427.2,317.1) 0(1427.25,301.35) 0(1427.25,332.85) 0(1427.25,348.6)

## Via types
v1: diameter 19.68, hole 7.87, Component Side 1 to Solder Side 4, 4 vias

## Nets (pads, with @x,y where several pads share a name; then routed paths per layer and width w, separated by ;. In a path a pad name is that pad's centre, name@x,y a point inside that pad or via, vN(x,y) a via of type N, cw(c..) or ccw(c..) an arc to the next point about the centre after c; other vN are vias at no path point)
+3.3V: C23.1 J6.2 JP1.1 pad.0@370,1405 pad.0@390,1425 | length 1760.2
  Component Side 1 w20: JP1.1@240,1325 340,1325 355,1340 355,1390 pad.0@370,1405 pad.0@390,1425 430,1465 C23.1@430,1512.76
  Solder Side 4 w30: pad.0@370,1405 pad.0@390,1425 477,1425 514,1462 902,1462 1105,1665 1590,1665 1620,1635 J6.2@1620,1570
+5V: C14.1 J4.2 JP1.2 | length 1306
  Component Side 1 w20: C14.1@530,1512.76 530,1325 JP1.2@510,1325 425,1325 400,1300 400,1100 425,1075 575,1075 597.43,1052.57 597.43,574.54 621.97,550 J4.2@670,550
AC1: C1.2 C2.2 C6.2 C9.1 C10.1 C11.1 C12.1 C13.1 U1.B3 U1.B4 | length 225.8
  Component Side 1 w8: U1.B3@1411.5,317.13 U1.B4@1411.5,301.38 1411.5,288.5 1415,285
  Component Side 1 w12: 1415,285 1415.15,284.85 1434.08,284.85 1434.24,285 1455,285 1496.38,326.38 1590,326.38
AC2: C11.2 C12.2 C15.2 C19.2 C20.2 J3.1 U1.B1 U1.B2 | length 213.4
  Component Side 1 w8: U1.B2@1411.5,332.87 U1.B1@1411.5,348.62 1411.5,361.5 1415,365
  Component Side 1 w12: 1415,365 1415.15,365.15 1434.09,365.15 1434.24,365 1485,365 1495,375 1588.62,375 1590,373.62
ADC_IN: C29.1 JP1.11 R23.1 R24.2 | length 284.1
  Component Side 1 w12: C29.1@129,779 129,815 139,825 182,825 ; R24.2@182,779 182,825 ; R23.1@182,862 182,825 ; JP1.11@290,825 182,825
BOOT1: C6.1 U1.C4 | length 186.2
  Component Side 1 w8: U1.C4@1395.75,301.38 1395.75,281.53 1408.52,268.85 1440.71,268.85 1440.87,269 1555.38,269 C6.1@1556.38,270
BOOT2: C20.1 U1.C1 | length 196.4
  Component Side 1 w8: U1.C1@1395.75,348.62 1395.75,369.25 1407.65,381.15 1471.15,381.15 1520,430 C20.1@1546.38,430
CHG: D1.2 U1.F4 | length 121.5
  Component Side 1 w8: D1.2@1300,200 1300,240 1348.5,288.5 U1.F4@1348.5,301.38
CLMP1: C2.1 pad.0@1364.25,317.1 pad.0@1505,220 U1.E3 | length 239.9
  Component Side 1 w8: pad.0@1505,220 C2.1@1548.5,220
  Solder Side 4 w8: pad.0@1364.25,317.1 1364.25,290.75 1400,255 1455,255 1490,220 pad.0@1505,220
CLMP2: C19.1 pad.0@1364.25,332.85 pad.0@1495,480 U1.E2 | length 282.9
  Component Side 1 w8: pad.0@1495,480 C19.1@1538.5,480
  Solder Side 4 w8: pad.0@1364.25,332.85 1364.25,359.25 1400,395 1430,395 1450,415 1450,470 1460,480 pad.0@1495,480
COMM1: C1.1 U1.E4 | length 267.4
  Component Side 1 w8: U1.E4@1364.25,301.38 1364.25,290.75 1405,250 1440,250 1475,215 1475,190 1495,170 C1.1@1556.38,170
COMM2: C15.1 U1.E1 | length 324
  Component Side 1 w8: U1.E1@1364.25,348.62 1364.25,357.55 1401.85,395.15 1460.15,395.15 1470,405 1470,510 1490,530 C15.1@1546.38,530
GND: C3.2 C4.2 C5.2 C7.2 C8.2 C14.2 C16.2 C17.2 C18.2 C21.2 C22.2 C23.2 C24.2 C25.2 C27.2 C28.2 C29.2 J2.2 JP1.4 JP2.2 pad.0@182,687 pad.0@375,1650 pad.0@400,75 pad.0@430,1610 pad.0@480,1175 pad.0@520,1175 pad.0@530,1610 pad.0@570,1400 pad.0@659,1141 pad.0@714,1117 pad.0@720,1520 pad.0@770,1110 pad.0@799,1257 pad.0@860,1030 pad.0@950,1410 pad.0@980,1310 pad.0@1040,1285 pad.0@1070,870 pad.0@1215,875 pad.0@1230,515 pad.0@1260,300 pad.0@1280,875 pad.0@1290,535 pad.0@1332.7,317.1 pad.0@1332.75,332.85 pad.0@1332.76,301.38 pad.0@1356,1096 pad.0@1360,120 pad.0@1405,120 pad.0@1405,515 pad.0@1427.2,317.1 pad.0@1427.25,301.35 pad.0@1427.25,332.85 pad.0@1427.25,348.6 pad.0@1462.5,1300 pad.0@1490,1300 pad.0@1785,885 pad.0@1785,1195 pad.0@1835,885 pad.0@1835,1160 pad.0@1870,1060 pad.0@1895,920 pad.0@2100,75 pad.0@2100,1600 pad.0@2292,1325 pad.0@2325,1325 R1.1 R2.1 R3.1 R6.1 R9.1 R10.1 R11.1 R16.1 R17.1 R19.1 R20.1 R24.1 U1.A1 U1.A2 U1.A3 U1.A4 U1.G2 U1.G3 U1.G4 U2.C2 U3.3 U4.5 U4.12 U4.15 | length 2176.2
  Component Side 1 w8: U4.5@1003.04,1056.31 1048.31,1056.31 U4.15@1068,1076 1087.68,1095.68 U4.12@1132.96,1095.68 ; R9.1@1223.62,300 pad.0@1260,300 ; U1.G4@1332.76,301.38 U1.G3@1332.76,317.13 U1.G2@1332.76,332.87 ; pad.0@1360,120 C4.2@1360,152.76 ; pad.0@1405,120 C3.2@1405,152.76 ; R6.1@1405,478.62 pad.0@1405,515 ; U1.A4@1427.24,301.38 U1.A3@1427.24,317.13 U1.A2@1427.24,332.87 U1.A1@1427.24,348.62 ; pad.0@1835,885 R1.1@1835,922.76 ; U2.C2@1846.5,1035.75 1860,1049.25 ; R3.1@1895,966.38 R3.1@1895,970
  Component Side 1 w10: pad.0@1490,1300 1610,1300 1710,1200 1710,985 1700,975 1690,975 1680,985 R19.1@1680,1011.38
  Component Side 1 w15: R10.1@720,1487.24 pad.0@720,1520 ; pad.0@770,1110 R11.1@770,1152.76 ; pad.0@860,1030 R17.1@902.76,1030 ; C18.2@902.99,1410 pad.0@950,1410 ; C7.2@1230,478.62 pad.0@1230,515 ; C8.2@1290,492.99 pad.0@1290,535 ; R20.1@1480,1258.62 pad.0@1490,1300 ; R2.1@1835,1127.24 pad.0@1835,1160 ; pad.0@1895,920 R3.1@1895,966.38
  Component Side 1 w20: pad.0@182,687 R24.1@182,731.76 ; C23.2@430,1560 pad.0@430,1610 ; JP1.4@460,1225 JP1.4@510,1225 520,1215 pad.0@520,1175 pad.0@480,1175 ; C14.2@530,1560 pad.0@530,1610 ; pad.0@659,1141 C16.2@660,1176.38 ; pad.0@714,1117 C17.2@715,1157.5 ; C22.2@980,1261.5 pad.0@980,1310 ; C21.2@1040,1243.62 pad.0@1040,1285 ; pad.0@1070,870 R16.1@1070,912.76 ; pad.0@1785,885 C5.2@1785,922.76 ; C27.2@1785,1158.62 pad.0@1785,1195 ; 1860,1049.25 pad.0@1870,1059.25 ; JP2.2@2210,1325 pad.0@2292,1325 pad.0@2325,1325
  Signal Layer 2 w8: pad.0@1427.25,301.35 pad.0@1427.25,332.85 pad.0@1427.25,348.6
  Signal Layer 3 w8: pad.0@1427.25,301.35 pad.0@1427.25,332.85 pad.0@1427.25,348.6
  Solder Side 4 w8: pad.0@1427.25,297.75 pad.0@1427.25,301.35 pad.0@1427.25,332.85 pad.0@1427.25,348.6
  other v1: 1068,1045.49 1037.49,1076 1098.51,1076 1068,1106.51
